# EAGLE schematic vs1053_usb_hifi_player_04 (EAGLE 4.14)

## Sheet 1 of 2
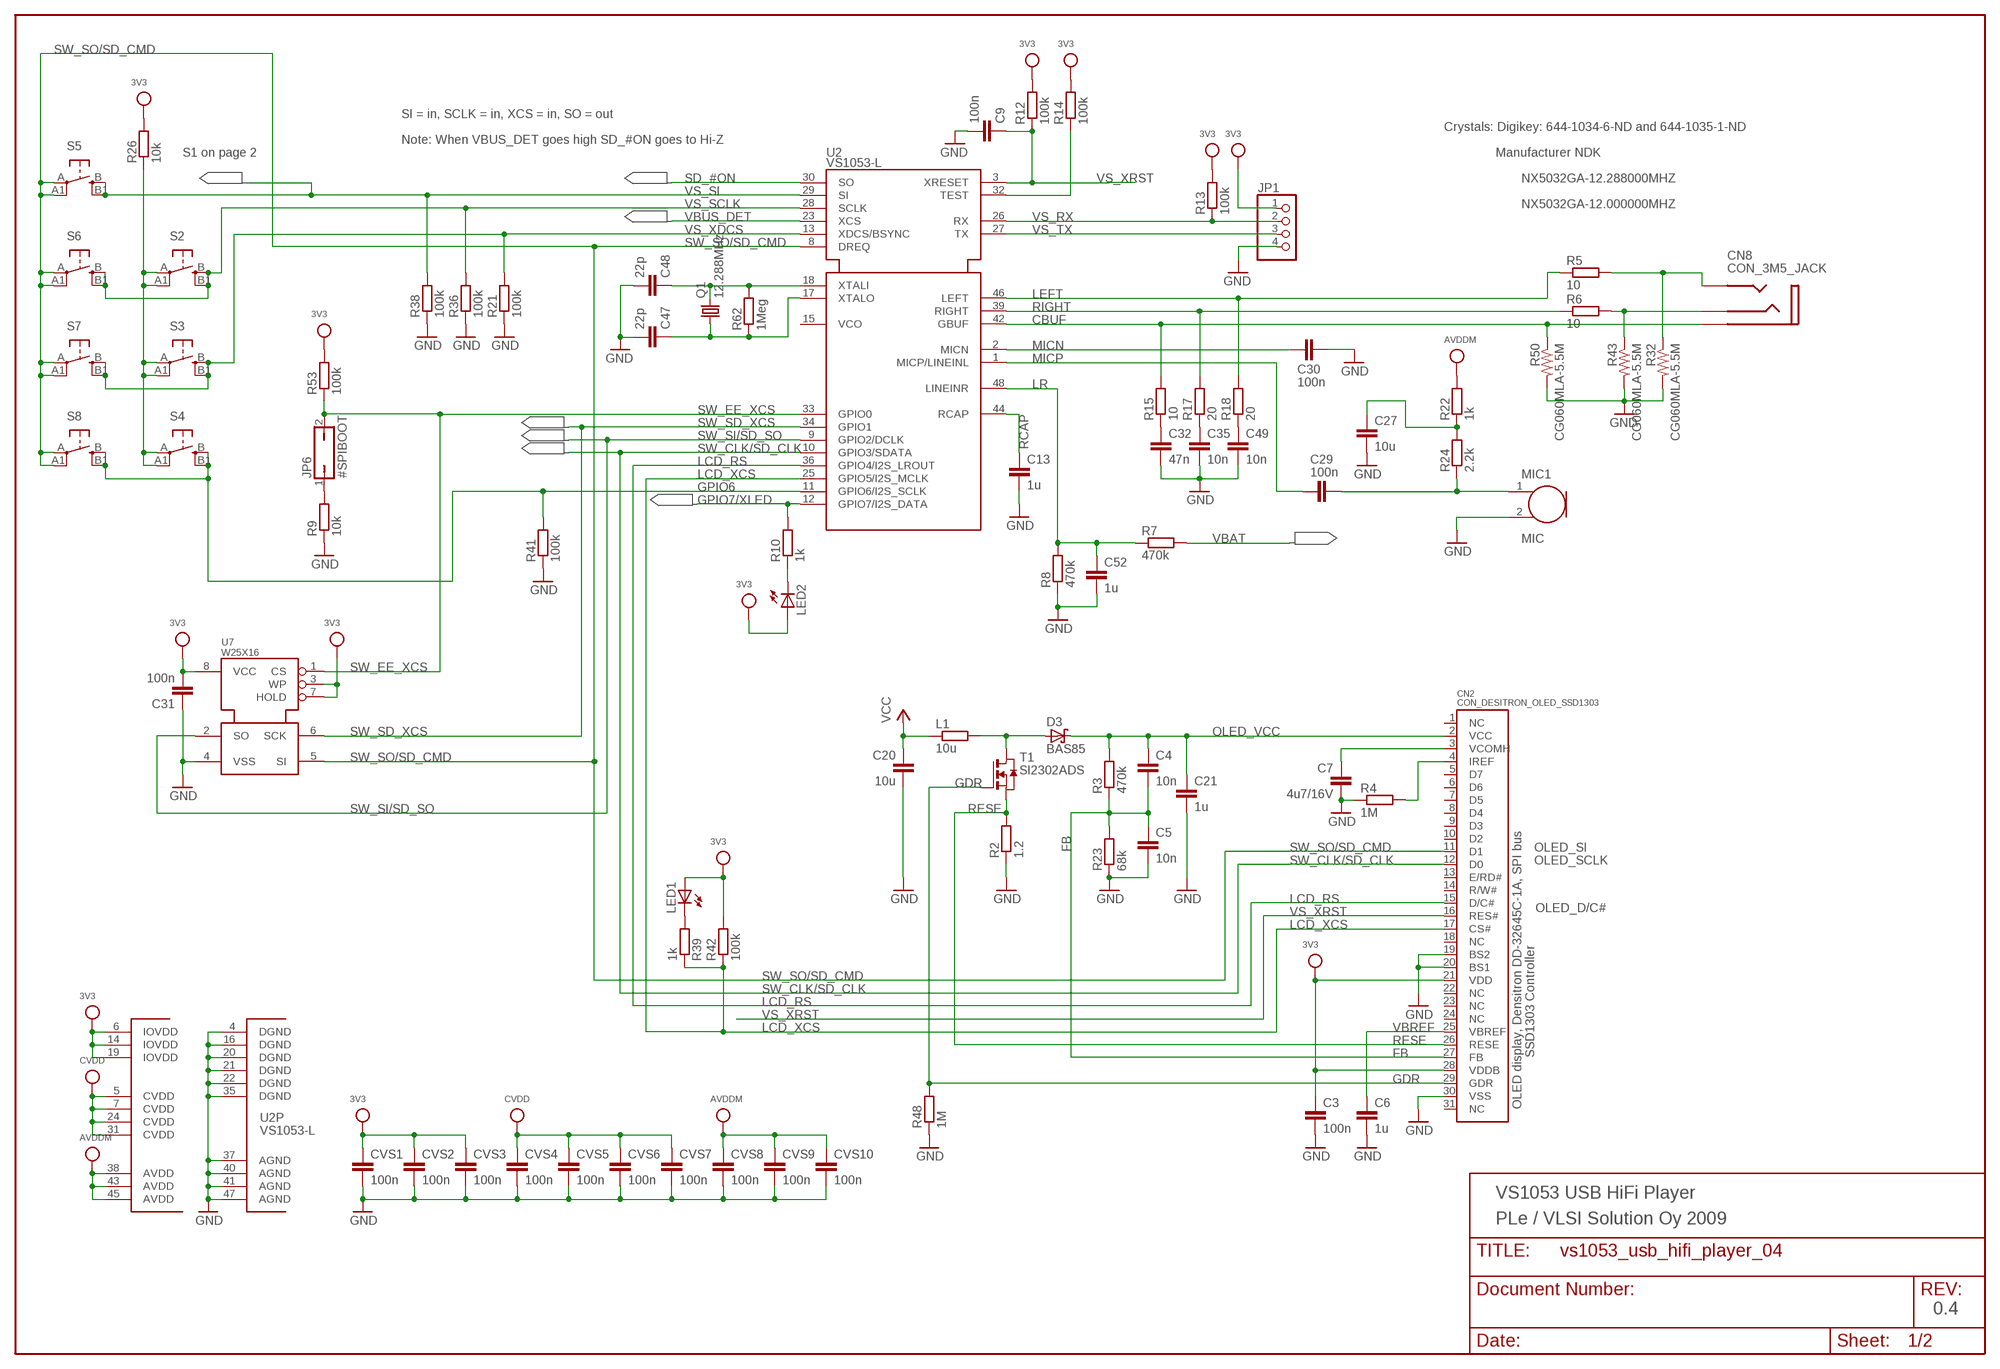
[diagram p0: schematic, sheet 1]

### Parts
C3  100n  C-EUC0603  [C0603]
C4  10n  C-EUC0603  [C0603]
C5  10n  C-EUC0603  [C0603]
C6  1u  C-EUC0603  [C0603]
C7  4u7/16V  C-EUC0805K  [C0805K]
C9  100n  C-EUC0603  [C0603]
C13  1u  C-EUC0603  [C0603]
C20  10u  C-EUC0805K  [C0805K]
C21  1u  C-EUC0603  [C0603]
C27  10u  C-EUC0805K  [C0805K]
C29  100n  C-EUC0603  [C0603]
C30  100n  C-EUC0603  [C0603]
C31  100n  C-EUC0603  [C0603]
C32  47n  C-EUC0603  [C0603]
C35  10n  C-EUC0603  [C0603]
C47  22p  C-EUC0603  [C0603]
C48  22p  C-EUC0603  [C0603]
C49  10n  C-EUC0603  [C0603]
C52  1u  C-EUC0603  [C0603]
CN2  CON_DESITRON_OLED_SSD1303  [CON_DESITRON_OLED]
CN8  CON_3M5_JACK  [CON_3M5_JACK_SMD]
CVS1  100n  C-EUC0603  [C0603]
CVS2  100n  C-EUC0603  [C0603]
CVS3  100n  C-EUC0603  [C0603]
CVS4  100n  C-EUC0603  [C0603]
CVS5  100n  C-EUC0603  [C0603]
CVS6  100n  C-EUC0603  [C0603]
CVS7  100n  C-EUC0603  [C0603]
CVS8  100n  C-EUC0603  [C0603]
CVS9  100n  C-EUC0603  [C0603]
CVS10  100n  C-EUC0603  [C0603]
D3  BAS85  [SOD80]
JP1  PINHD-1X4  [1X04]
JP6  #SPIBOOT  JP1Q  [JP1]
L1  10u  R-EU_R1210  [R1210]
LED1  LEDCHIPLED_0805  [CHIPLED_0805]
LED2  LEDCHIPLED_0805  [CHIPLED_0805]
MIC1  MIC  [MIC]
Q1  12.288MHz  CRYTAL  [CRYSTAL_5X3.2]
R2  1.2  R-EU_R0805  [R0805]
R3  470k  R-EU_R0603  [R0603]
R4  1M  R-EU_R0603  [R0603]
R5  10  R-EU_R0603  [R0603]
R6  10  R-EU_R0603  [R0603]
R7  470k  R-EU_R0603  [R0603]
R8  470k  R-EU_R0603  [R0603]
R9  10k  R-EU_R0603  [R0603]
R10  1k  R-EU_R0603  [R0603]
R12  100k  R-EU_R0603  [R0603]
R13  100k  R-EU_R0603  [R0603]
R14  100k  R-EU_R0603  [R0603]
R15  10  R-EU_R0603  [R0603]
R17  20  R-EU_R0603  [R0603]
R18  20  R-EU_R0603  [R0603]
R21  100k  R-EU_R0603  [R0603]
R22  1k  R-EU_R0603  [R0603]
R23  68k  R-EU_R0603  [R0603]
R24  2.2k  R-EU_R0603  [R0603]
R26  10k  R-EU_R0603  [R0603]
R32  CG060MLA-5.5M  R-US_R0603  [R0603]
R36  100k  R-EU_R0603  [R0603]
R38  100k  R-EU_R0603  [R0603]
R39  1k  R-EU_R0603  [R0603]
R41  100k  R-EU_R0603  [R0603]
R42  100k  R-EU_R0603  [R0603]
R43  CG060MLA-5.5M  R-US_R0603  [R0603]
R48  1M  R-EU_R0603  [R0603]
R50  CG060MLA-5.5M  R-US_R0603  [R0603]
R53  100k  R-EU_R0603  [R0603]
R62  1Meg  R-EU_R0603  [R0603]
S2  SW_MICROS  [SW_EVQ]
S3  SW_MICROS  [SW_EVQ]
S4  SW_MICROS  [SW_EVQ]
S5  SW_MICROS  [SW_EVQ]
S6  SW_MICROS  [SW_EVQ]
S7  SW_MICROS  [SW_EVQ]
S8  SW_MICROS  [SW_EVQ]
T1  SI2302ADS  [SOT23]
U2  VS1053-L  [LQFP48]
U7  W25X16  25LC640SOM  [SO-08M]

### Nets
3V3: C3.1 C31.2 CN2.21(VDD) CN2.28(VDDB) CVS1.1 CVS2.1 CVS3.1 JP1.1 LED1.A LED2.A R12.2 R13.2 R14.2 R26.2 R42.2 R53.2 U2.6(IOVDD) U2.14(IOVDD) U2.19(IOVDD) U7.3(WP) U7.7(HOLD) U7.8(VCC) ; also sheet 2
AVDDM: CVS8.1 CVS9.1 CVS10.1 R22.2 U2.38(AVDD) U2.43(AVDD) U2.45(AVDD) ; also sheet 2
CBUF: CN8.SLEEVE(GND) R15.2 R50.1 U2.42(GBUF) ; also sheet 2
CVDD: CVS4.1 CVS5.1 CVS6.1 CVS7.1 U2.5(CVDD) U2.7(CVDD) U2.24(CVDD) U2.31(CVDD) ; also sheet 2
FB: C4.2 C5.1 CN2.27(FB) R3.1 R23.2
GDR: CN2.29(GDR) R48.2 T1.1(G)
GND: C3.2 C5.2 C6.2 C7.2 C9.2 C13.2 C20.2 C21.2 C27.2 C30.2 C31.1 C32.2 C35.2 C47.2 C48.2 C49.2 C52.2 CN2.19(BS2) CN2.20(BS1) CN2.30(VSS) CVS1.2 CVS2.2 CVS3.2 CVS4.2 CVS5.2 CVS6.2 CVS7.2 CVS8.2 CVS9.2 CVS10.2 JP1.4 MIC1.2 R2.1 R4.1 R8.1 R9.1 R21.1 R23.1 R32.2 R36.1 R38.1 R41.1 R43.2 R48.1 R50.2 U2.4(DGND) U2.16(DGND) U2.20(DGND) U2.21(DGND) U2.22(DGND) U2.35(DGND) U2.37(AGND) U2.40(AGND) U2.41(AGND) U2.47(AGND) U7.4(VSS) ; also sheet 2
GPIO6: R41.2 S4.B1(S1) S4.B(S) S8.B1(S1) S8.B(S) U2.11(GPIO6/I2S_SCLK)
GPIO7/XLED: R10.2 U2.12(GPIO7/I2S_DATA) ; also sheet 2
LCD_RS: CN2.15(D/C#) U2.36(GPIO4/I2S_LROUT)
LCD_XCS: CN2.17(CS#) R39.1 R42.1 U2.25(GPIO5/I2S_MCLK)
LEFT: R5.1 R18.2 U2.46(LEFT)
LR: C52.1 R7.1 R8.2 U2.48(LINEINR)
MICN: C30.1 U2.2(MICN)
MICP: C29.1 U2.1(MICP/LINEINL)
N$3: CN8.RING(RIGHT) R6.2 R43.1
N$4: CN8.TIP(LEFT) R5.2 R32.1
N$6: C7.1 CN2.3(VCOMH)
N$9: R26.1 S2.A1(P1) S2.A(P) S3.A1(P1) S3.A(P) S4.A1(P1) S4.A(P)
N$11: C27.1 R22.1 R24.2
N$13: LED2.C R10.1
N$17: C29.2 MIC1.1 R24.1
N$19: JP6.1 R9.2
N$20: D3.2(A) L1.2 T1.3(D)
N$44: LED1.C R39.2
N$47: R14.1 U2.32(TEST)
N$49: C32.1 R15.1
N$50: C35.1 R17.1
N$51: C49.1 R18.1
N$53: CN2.4(IREF) R4.2
OLED_VCC: C4.1 C21.1 CN2.2(VCC) D3.1(C) R3.2
RCAP: C13.1 U2.44(RCAP)
RESE: CN2.26(RESE) R2.2 T1.2(S)
RIGHT: R6.1 R17.2 U2.39(RIGHT)
SD_#ON: U2.30(SO) ; also sheet 2
SW_CLK/SD_CLK: CN2.12(D0) U2.10(GPIO3/SDATA) ; also sheet 2
SW_EE_XCS: JP6.2 R53.1 U2.33(GPIO0) U7.1(CS)
SW_SD_XCS: U2.34(GPIO1) U7.6(SCK) ; also sheet 2
SW_SI/SD_SO: U2.9(GPIO2/DCLK) U7.2(SO) ; also sheet 2
SW_SO/SD_CMD: CN2.11(D1) S5.A1(P1) S5.A(P) S6.A1(P1) S6.A(P) S7.A1(P1) S7.A(P) S8.A1(P1) S8.A(P) U2.8(DREQ) U7.5(SI) ; also sheet 2
VBAT: R7.2 ; also sheet 2
VBREF: C6.1 CN2.25(VBREF)
VBUS_DET: U2.23(XCS) ; also sheet 2
VCC: C20.1 L1.1 ; also sheet 2
VS_RX: JP1.2 R13.1 U2.26(RX)
VS_SCLK: R36.2 S2.B1(S1) S2.B(S) S6.B1(S1) S6.B(S) U2.28(SCLK)
VS_SI: R38.2 S5.B1(S1) S5.B(S) U2.29(SI) ; also sheet 2
VS_TX: JP1.3 U2.27(TX)
VS_XDCS: R21.2 S3.B1(S1) S3.B(S) S7.B1(S1) S7.B(S) U2.13(XDCS/BSYNC)
VS_XRST: C9.1 CN2.16(RES#) R12.1 U2.3(XRESET)
VS_XTALI: C48.1 Q1.P$2 R62.2 U2.18(XTALI)
VS_XTALO: C47.1 Q1.P$1 R62.1 U2.17(XTALO)
Unconnected: CN2.1(NC) CN2.5(D7) CN2.6(D6) CN2.7(D5) CN2.8(D4) CN2.9(D3) CN2.10(D2) CN2.13(E/RD#) CN2.14(R/W#) CN2.18(NC) CN2.22(NC) CN2.23(NC) CN2.24(NC) CN2.31(NC) U2.15(VCO)

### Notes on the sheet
- SI = in, SCLK = in, XCS = in, SO = out
- Crystals: Digikey: 644-1034-6-ND and 644-1035-1-ND
- Note: When VBUS_DET goes high SD_#ON goes to Hi-Z
- S1 on page 2 | Manufacturer	NDK
- NX5032GA-12.288000MHZ
- NX5032GA-12.000000MHZ
- OLED_SI
- OLED_SCLK
- OLED_D/C#
- SSD1303 Controller
- OLED display, Densitron DD-32645C-1A, SPI bus
- VS1053 USB HiFi Player
- PLe / VLSI Solution Oy 2009
- 0.4

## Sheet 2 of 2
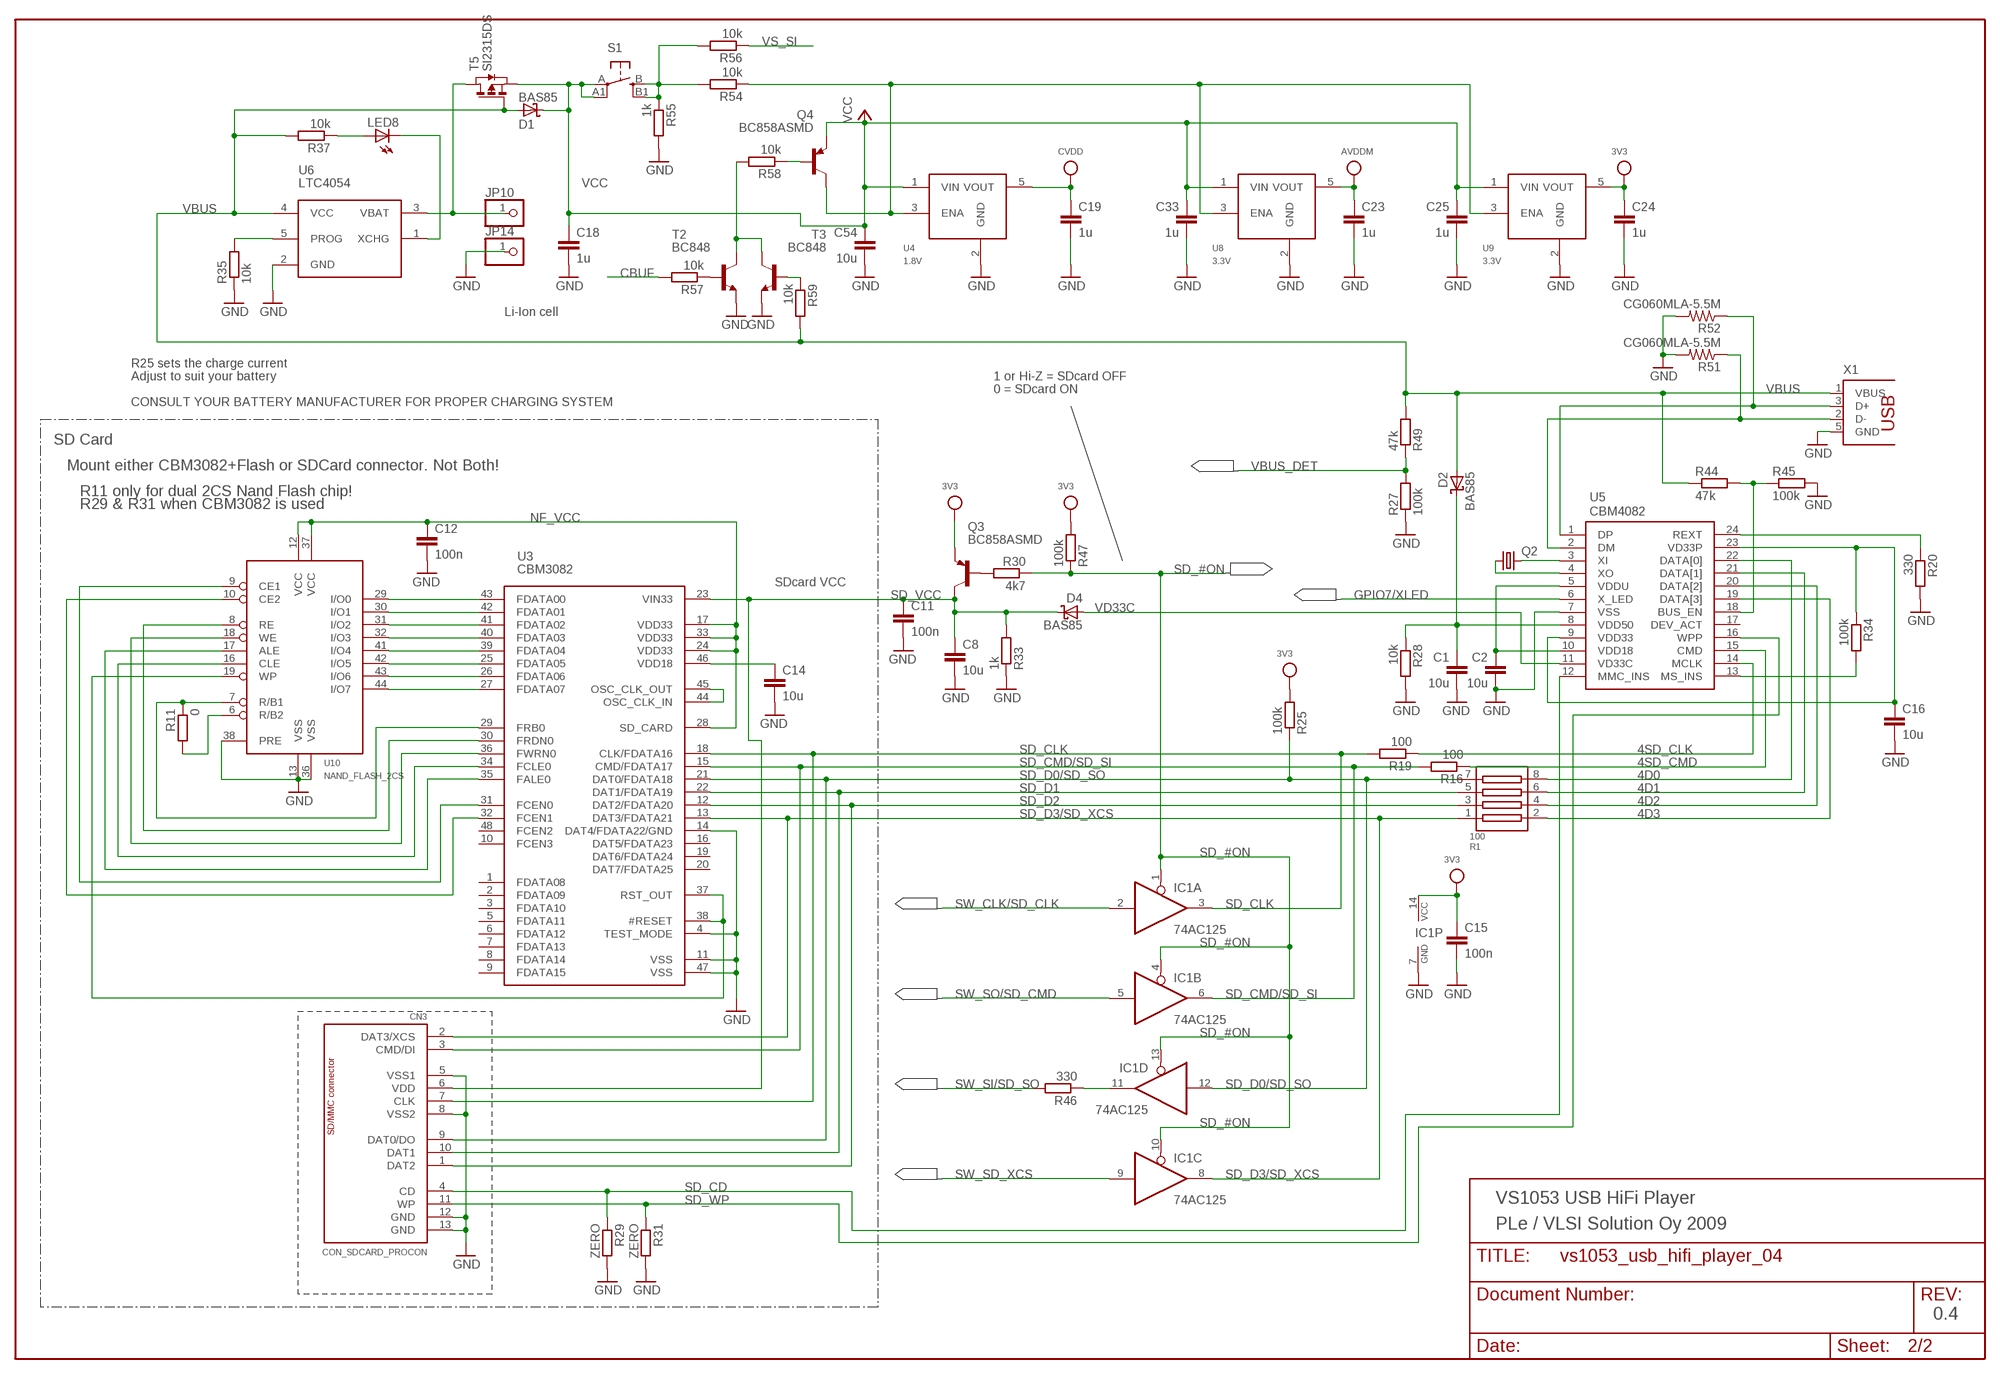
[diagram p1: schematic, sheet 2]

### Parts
C1  10u  C-EUC0805K  [C0805K]
C2  10u  C-EUC0805K  [C0805K]
C8  10u  C-EUC0805K  [C0805K]
C11  100n  C-EUC0603  [C0603]
C12  100n  C-EUC0603  [C0603]
C14  10u  C-EUC1206  [C1206]
C15  100n  C-EUC0603  [C0603]
C16  10u  C-EUC0805K  [C0805K]
C18  1u  C-EUC0603  [C0603]
C19  1u  C-EUC0603  [C0603]
C23  1u  C-EUC0603  [C0603]
C24  1u  C-EUC0603  [C0603]
C25  1u  C-EUC0603  [C0603]
C33  1u  C-EUC0603  [C0603]
C54  10u  C-EUC0805K  [C0805K]
CN3  CON_SDCARD_PROCON  [CON_SDCARD_PROCONN]
D1  BAS85  [SOD80]
D2  BAS85  [SOD80]
D4  BAS85  [SOD80]
IC1  74AC125  74ACT125  [TSSOP14]
JP10  PINHD-1X1  [1X01]
JP14  PINHD-1X1  [1X01]
LED8  LEDCHIPLED_0805  [CHIPLED_0805]
Q2  CRYTAL  [CRYSTAL_5X3.2]
Q3  BC858ASMD  [SOT23-BEC]
Q4  BC858ASMD  [SOT23-BEC]
R1  100  RES_ARR_1206  [RAS_ARR_1206]
R11  0  R-EU_R0603  [R0603]
R16  100  R-EU_R0603  [R0603]
R19  100  R-EU_R0603  [R0603]
R20  330  R-EU_R0603  [R0603]
R25  100k  R-EU_R0603  [R0603]
R27  100k  R-EU_R0603  [R0603]
R28  10k  R-EU_R0603  [R0603]
R29  ZERO  R-EU_R0603  [R0603]
R30  4k7  R-EU_R0603  [R0603]
R31  ZERO  R-EU_R0603  [R0603]
R33  1k  R-EU_R0603  [R0603]
R34  100k  R-EU_R0603  [R0603]
R35  10k  R-EU_R0603  [R0603]
R37  10k  R-EU_R0603  [R0603]
R44  47k  R-EU_R0603  [R0603]
R45  100k  R-EU_R0603  [R0603]
R46  330  R-EU_R0603  [R0603]
R47  100k  R-EU_R0603  [R0603]
R49  47k  R-EU_R0603  [R0603]
R51  CG060MLA-5.5M  R-US_R0603  [R0603]
R52  CG060MLA-5.5M  R-US_R0603  [R0603]
R54  10k  R-EU_R0603  [R0603]
R55  1k  R-EU_R0603  [R0603]
R56  10k  R-EU_R0603  [R0603]
R57  10k  R-EU_R0603  [R0603]
R58  10k  R-EU_R0603  [R0603]
R59  10k  R-EU_R0603  [R0603]
S1  SW_MICROS  [SW_EVQ]
T2  BC848  [SOT23]
T3  BC848  [SOT23]
T5  SI2315DS  [SOT23]
U3  CBM3082  [LQFP48]
U4  1.8V  ZXCL280E5TA  [SOT23-5L]
U5  CBM4082  [QSOP24]
U6  LTC4054  [SOT23-5L]
U8  3.3V  ZXCL280E5TA  [SOT23-5L]
U9  3.3V  ZXCL280E5TA  [SOT23-5L]
U10  NAND_FLASH_2CS  [TSOP48L]
X1  CON_USB_B  [MINI_USB_MOLEX]

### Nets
3V3: C15.1 C24.1 IC1.14(P:VCC) Q3.E R25.2 R47.2 U9.5(VOUT) ; also sheet 1
4D0: R1.8 U5.22(DATA[0])
4D1: R1.6 U5.21(DATA[1])
4D2: R1.4 U5.20(DATA[2])
4D3: R1.2 U5.19(DATA[3])
4SD_CLK: R19.1 U5.14(MCLK)
4SD_CMD: R16.1 U5.15(CMD)
AVDDM: C23.1 U8.5(VOUT) ; also sheet 1
CBUF: R57.2 ; also sheet 1
CVDD: C19.1 U4.5(VOUT) ; also sheet 1
GND: C1.2 C2.2 C8.2 C11.2 C12.2 C14.2 C15.2 C16.2 C18.2 C19.2 C23.2 C24.2 C25.2 C33.2 C54.2 CN3.5(VSS1) CN3.8(VSS2) CN3.12(GND) CN3.13(GND) IC1.7(P:GND) JP14.1 R20.2 R27.1 R28.2 R29.2 R31.2 R33.1 R35.1 R45.2 R51.2 R52.2 R55.2 T2.2(E) T3.2(E) U3.4(TEST_MODE) U3.11(VSS) U3.14(DAT4/FDATA22/GND) U3.47(VSS) U4.2(GND) U5.7(VSS) U6.2(GND) U8.2(GND) U9.2(GND) U10.13(VSS) U10.36(VSS) U10.38(PRE) X1.5(GND) ; also sheet 1
GPIO7/XLED: U5.6(X_LED) ; also sheet 1
N$1: U3.32(FCEN1) U10.10(CE2)
N$2: U3.43(FDATA00) U10.29(I/O0)
N$5: U3.42(FDATA01) U10.30(I/O1)
N$7: U3.41(FDATA02) U10.31(I/O2)
N$8: U3.40(FDATA03) U10.32(I/O3)
N$10: U3.39(FDATA04) U10.41(I/O4)
N$12: U3.25(FDATA05) U10.42(I/O5)
N$14: U3.26(FDATA06) U10.43(I/O6)
N$15: U3.27(FDATA07) U10.44(I/O7)
N$16: U3.31(FCEN0) U10.9(CE1)
N$18: R11.1 U3.29(FRB0) U10.7(R/B1)
N$21: U3.30(FRDN0) U10.8(RE)
N$22: U3.36(FWRN0) U10.18(WE)
N$23: U3.34(FCLE0) U10.16(CLE)
N$24: U3.35(FALE0) U10.17(ALE)
N$25: U3.44(OSC_CLK_IN) U3.45(OSC_CLK_OUT)
N$26: IC1.11(D:O) R46.1
N$27: Q3.B R30.2
N$28: R52.1 U5.1(DP) X1.3(D+)
N$29: R54.2 R55.1 R56.2 S1.B1(S1) S1.B(S)
N$30: C14.1 U3.46(VDD18)
N$32: R34.2 U5.13(MS_INS)
N$33: C16.1 R34.1 U5.9(VDD33) U5.23(VD33P)
N$34: C1.1 D2.1(C) R28.1 U5.8(VDD50)
N$36: R35.2 U6.5(PROG)
N$37: LED8.A R37.1
N$38: U3.37(RST_OUT) U3.38(#RESET) U10.19(WP)
N$39: Q2.P$2 U5.3(XI)
N$40: Q2.P$1 U5.4(XO)
N$41: R20.1 U5.24(REXT)
N$42: Q4.B R58.1
N$43: R51.1 U5.2(DM) X1.2(D-)
N$45: R58.2 T2.3(C) T3.3(C)
N$46: C2.1 U5.5(VDDU) U5.10(VDD18)
N$48: R57.1 T2.1(B)
N$52: Q4.C R54.1 U4.3(ENA) U8.3(ENA) U9.3(ENA)
N$54: R44.2 R45.1 U5.18(BUS_EN)
N$55: R59.1 T3.1(B)
NF_VCC: C12.1 U3.17(VDD33) U3.24(VDD33) U3.28(SD_CARD) U3.33(VDD33) U10.12(VCC) U10.37(VCC)
R/B2: R11.2 U10.6(R/B2)
SD_#ON: IC1.1(A:OE) IC1.4(B:OE) IC1.10(C:OE) IC1.13(D:OE) R30.1 R47.1 ; also sheet 1
SD_CD: CN3.4(CD) R29.1 U5.12(MMC_INS)
SD_CLK: CN3.7(CLK) IC1.3(A:O) R19.2 U3.18(CLK/FDATA16)
SD_CMD/SD_SI: CN3.3(CMD/DI) IC1.6(B:O) R16.2 U3.15(CMD/FDATA17)
SD_D0/SD_SO: CN3.9(DAT0/DO) IC1.12(D:I) R1.7 R25.1 U3.21(DAT0/FDATA18)
SD_D1: CN3.10(DAT1) R1.5 U3.22(DAT1/FDATA19)
SD_D2: CN3.1(DAT2) R1.3 U3.12(DAT2/FDATA20)
SD_D3/SD_XCS: CN3.2(DAT3/XCS) IC1.8(C:O) R1.1 U3.13(DAT3/FDATA21)
SD_VCC: C8.1 C11.1 CN3.6(VDD) D4.1(C) Q3.C R33.2 U3.23(VIN33)
SD_WP: CN3.11(WP) R31.1 U5.16(WPP)
SW_CLK/SD_CLK: IC1.2(A:I) ; also sheet 1
SW_SD_XCS: IC1.9(C:I) ; also sheet 1
SW_SI/SD_SO: R46.2 ; also sheet 1
SW_SO/SD_CMD: IC1.5(B:I) ; also sheet 1
VBAT: JP10.1 T5.3(D) U6.3(VBAT) ; also sheet 1
VBUS: D1.2(A) D2.2(A) R37.2 R44.1 R49.2 R59.2 T5.1(G) U6.4(VCC) X1.1(VBUS)
VBUS_DET: R27.2 R49.1 ; also sheet 1
VCC: C18.1 C25.1 C33.1 C54.1 D1.1(C) Q4.E S1.A1(P1) S1.A(P) T5.2(S) U4.1(VIN) U8.1(VIN) U9.1(VIN) ; also sheet 1
VD33C: D4.2(A) U5.11(VD33C)
VS_SI: R56.1 ; also sheet 1
XCHG: LED8.C U6.1(XCHG)
Unconnected: U3.1(FDATA08) U3.2(FDATA09) U3.3(FDATA10) U3.5(FDATA11) U3.6(FDATA12) U3.7(FDATA13) U3.8(FDATA14) U3.9(FDATA15) U3.10(FCEN3) U3.16(DAT5/FDATA23) U3.19(DAT6/FDATA24) U3.20(DAT7/FDATA25) U3.48(FCEN2) U5.17(DEV_ACT)

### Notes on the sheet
- Li-Ion cell
- R25 sets the charge current
- Adjust to suit your battery | 1 or Hi-Z = SDcard OFF
- 0 = SDcard ON
- CONSULT YOUR BATTERY MANUFACTURER FOR PROPER CHARGING SYSTEM
- SD Card
- Mount either CBM3082+Flash or SDCard connector. Not Both!
- R11 only for dual 2CS Nand Flash chip!
- R29 & R31 when CBM3082 is used
- SDcard VCC
- VS1053 USB HiFi Player
- PLe / VLSI Solution Oy 2009
- 0.4

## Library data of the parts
C1-C9 C11-C16 C18-C21 C23-C25 C27 C29-C33 C35 C47-C49 C52 C54 CVS1-CVS10 = rcl:C-EU: CAPACITOR, European symbol
CN2 = Omat_komponentit:CON_DESITRON_OLED_SSD1303
CN3 = Omat_komponentit:CON_SDCARD_PROCON
CN8 = Omat_komponentit:CON_3M5_JACK: Through hole: elfa: 42-701-04 huom. pädi on aivan varmasti väärin!!! mittaa työnärillä kun saat liittimiä... SMD liitin: Lumberg 1503 03 Farnell: 1216980
D1-D4 = Omat_komponentit:BAS85
IC1 = Omat_komponentit:74*125: Quad bus BUFFER, 3-state
JP1 = pinhead:PINHD-1X4: PIN HEADER
JP6 = jumper:JP1Q: JUMPER
JP10 JP14 = pinhead:PINHD-1X1: PIN HEADER
L1 R2-R31 R33-R39 R41 R42 R44-R49 R53-R59 R62 = rcl:R-EU_: RESISTOR, European symbol
LED1 LED2 LED8 = led:LED: LED
MIC1 = testaus:MIC
Q1 Q2 = Omat_komponentit:CRYTAL: CRYSTAL
Q3 Q4 = transistor-pnp:BC858*: PNP Transistror
R1 = Omat_komponentit:RES_ARR_1206
R32 R43 R50-R52 = rcl:R-US_: RESISTOR, American symbol
S1-S8 = Omat_komponentit:SW_MICRO: Panasonic EVQQ2 (EVQQ2B03W) farnell: 996-2832
T1 = Omat_komponentit:SI2302ADS: MOS FET
T2 T3 = transistor:BC848: NPN TRANSISTOR
T5 = Omat_komponentit:SI2315DS
U2 = vlsi:VS1053
U3 = Omat_komponentit:CBM3082
U4 U8 U9 = Omat_komponentit:ZXCL280E5TA
U5 = Omat_komponentit:CBM4082
U6 = Omat_komponentit:LTC4054
U7 = Omat_komponentit:25LC640
U10 = Omat_komponentit:NAND_FLASH_2CS
X1 = Omat_komponentit:CON_USB_B: BERG USB connector Mini USB B smt con: Farnell: 1125348 Molex 675031020 SOCKET, USB MINI-B SMT W/PEGS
